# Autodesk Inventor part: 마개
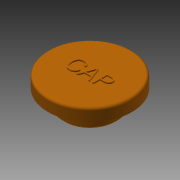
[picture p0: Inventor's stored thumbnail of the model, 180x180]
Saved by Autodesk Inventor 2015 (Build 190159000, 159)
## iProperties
Created: 2018-03
Part Number: 마개
Material: 고무
Document SubType Name: Modeling
Designer: mduedu
Density: 1 g/cm^3
Appearance: 주황색
Author: mduedu
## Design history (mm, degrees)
sketch "스케치1"
  geometry: C1 r 17 at (0, 0); 1 further point
  constraints: 1 centre point, 1 coincident
  dimensions: "d21" = 34 diameter of C1
extrude "돌출1" new body sketch "스케치1" distance "d2" = 6; taper "d3" = 0 deg
fillet "모깎기4" dims "d22" = 1
sketch "스케치6"
  geometry: C1 r 11 at (0, 0); 1 further point
  constraints: 1 centre point, 1 coincident
  dimensions: "d23" = 22 diameter of C1
extrude "돌출5" join sketch "스케치6" distance "d24" = 6; taper "d25" = 0 deg
sketch "스케치7"
  geometry: C1 r 7.5 at (0, 0); 1 further point
  constraints: 1 centre point, 1 coincident
  dimensions: "d26" = 15 diameter of C1
extrude "돌출6" cut sketch "스케치7" distance "d27" = 6; taper "d28" = 0 deg
sketch "스케치8"
  geometry: C1 r 17 at (0, 0) reference; C2 r 14 at (0, 0); 1 further point
  constraints: 1 centre point, 1 coincident
  dimensions: "d37" = 28 diameter of C2
extrude "돌출7" cut sketch "스케치8" distance "d30" = 1; taper "d31" = 0 deg
fillet "모깎기5" dims "d32" = 1
chamfer "모따기2" distance "d33" = 1; stored, may be unused: second distance "d34" = 2, angle "d35" = 45 deg
sketch "스케치5"
  geometry: 2 further points
  constraints: 1 coincident, 1 other
feature "엠보싱1" sketch "스케치5" dims "d19" = 0.5, "d20" = 0
node "솔리드1"
